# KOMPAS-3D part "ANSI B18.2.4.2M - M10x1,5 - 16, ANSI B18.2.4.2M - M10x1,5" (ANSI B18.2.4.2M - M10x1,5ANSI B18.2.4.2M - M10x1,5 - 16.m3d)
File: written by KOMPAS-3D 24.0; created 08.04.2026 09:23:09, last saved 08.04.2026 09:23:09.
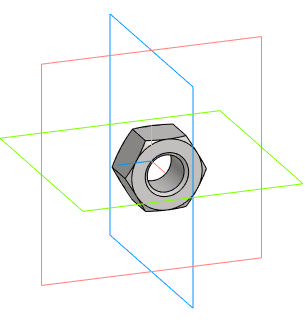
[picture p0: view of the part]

Document properties: Автор: Main; Полное имя файла: D:\DN.ru Аутсерс\Стекло смотровое DN.ru\Исходники\Стекло смотровое DN.ru SG2-34G-F тип В ГОСТ 21836-2021 Ду200 Ру16, углеродистая сталь, фланцевое\ANSI B18.2.4.2M - M10x1,5ANSI B18.2.4.2M - M10x1,5 - 16.m3d

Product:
- Body: Solid1  | qty 1
- Part/product: ANSI B18.2.4.2M - M10x1,5 - 16  | designation ANSI B18.2.4.2M - M10x1,5
    Комментарий: Типы метрических   шестигранных гаек   2
    additional columns: Сталь, мягкая

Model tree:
1. Solid1  (labels: Solid1)

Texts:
  ANSI B18.2.4.2M - M10x1,5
